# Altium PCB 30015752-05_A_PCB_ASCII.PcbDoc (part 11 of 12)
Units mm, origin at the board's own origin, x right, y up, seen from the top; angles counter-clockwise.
Board outline 100.05 x 72 mm, 10 copper layers (Top, GND_2, Signal_3, Signal_4, PWR_5, GND_6, Signal_7, Signal_8, GND_9, Bottom), stack 1.493 mm thick; 577 components, 546 nets, 2389 pads, 1412 vias.
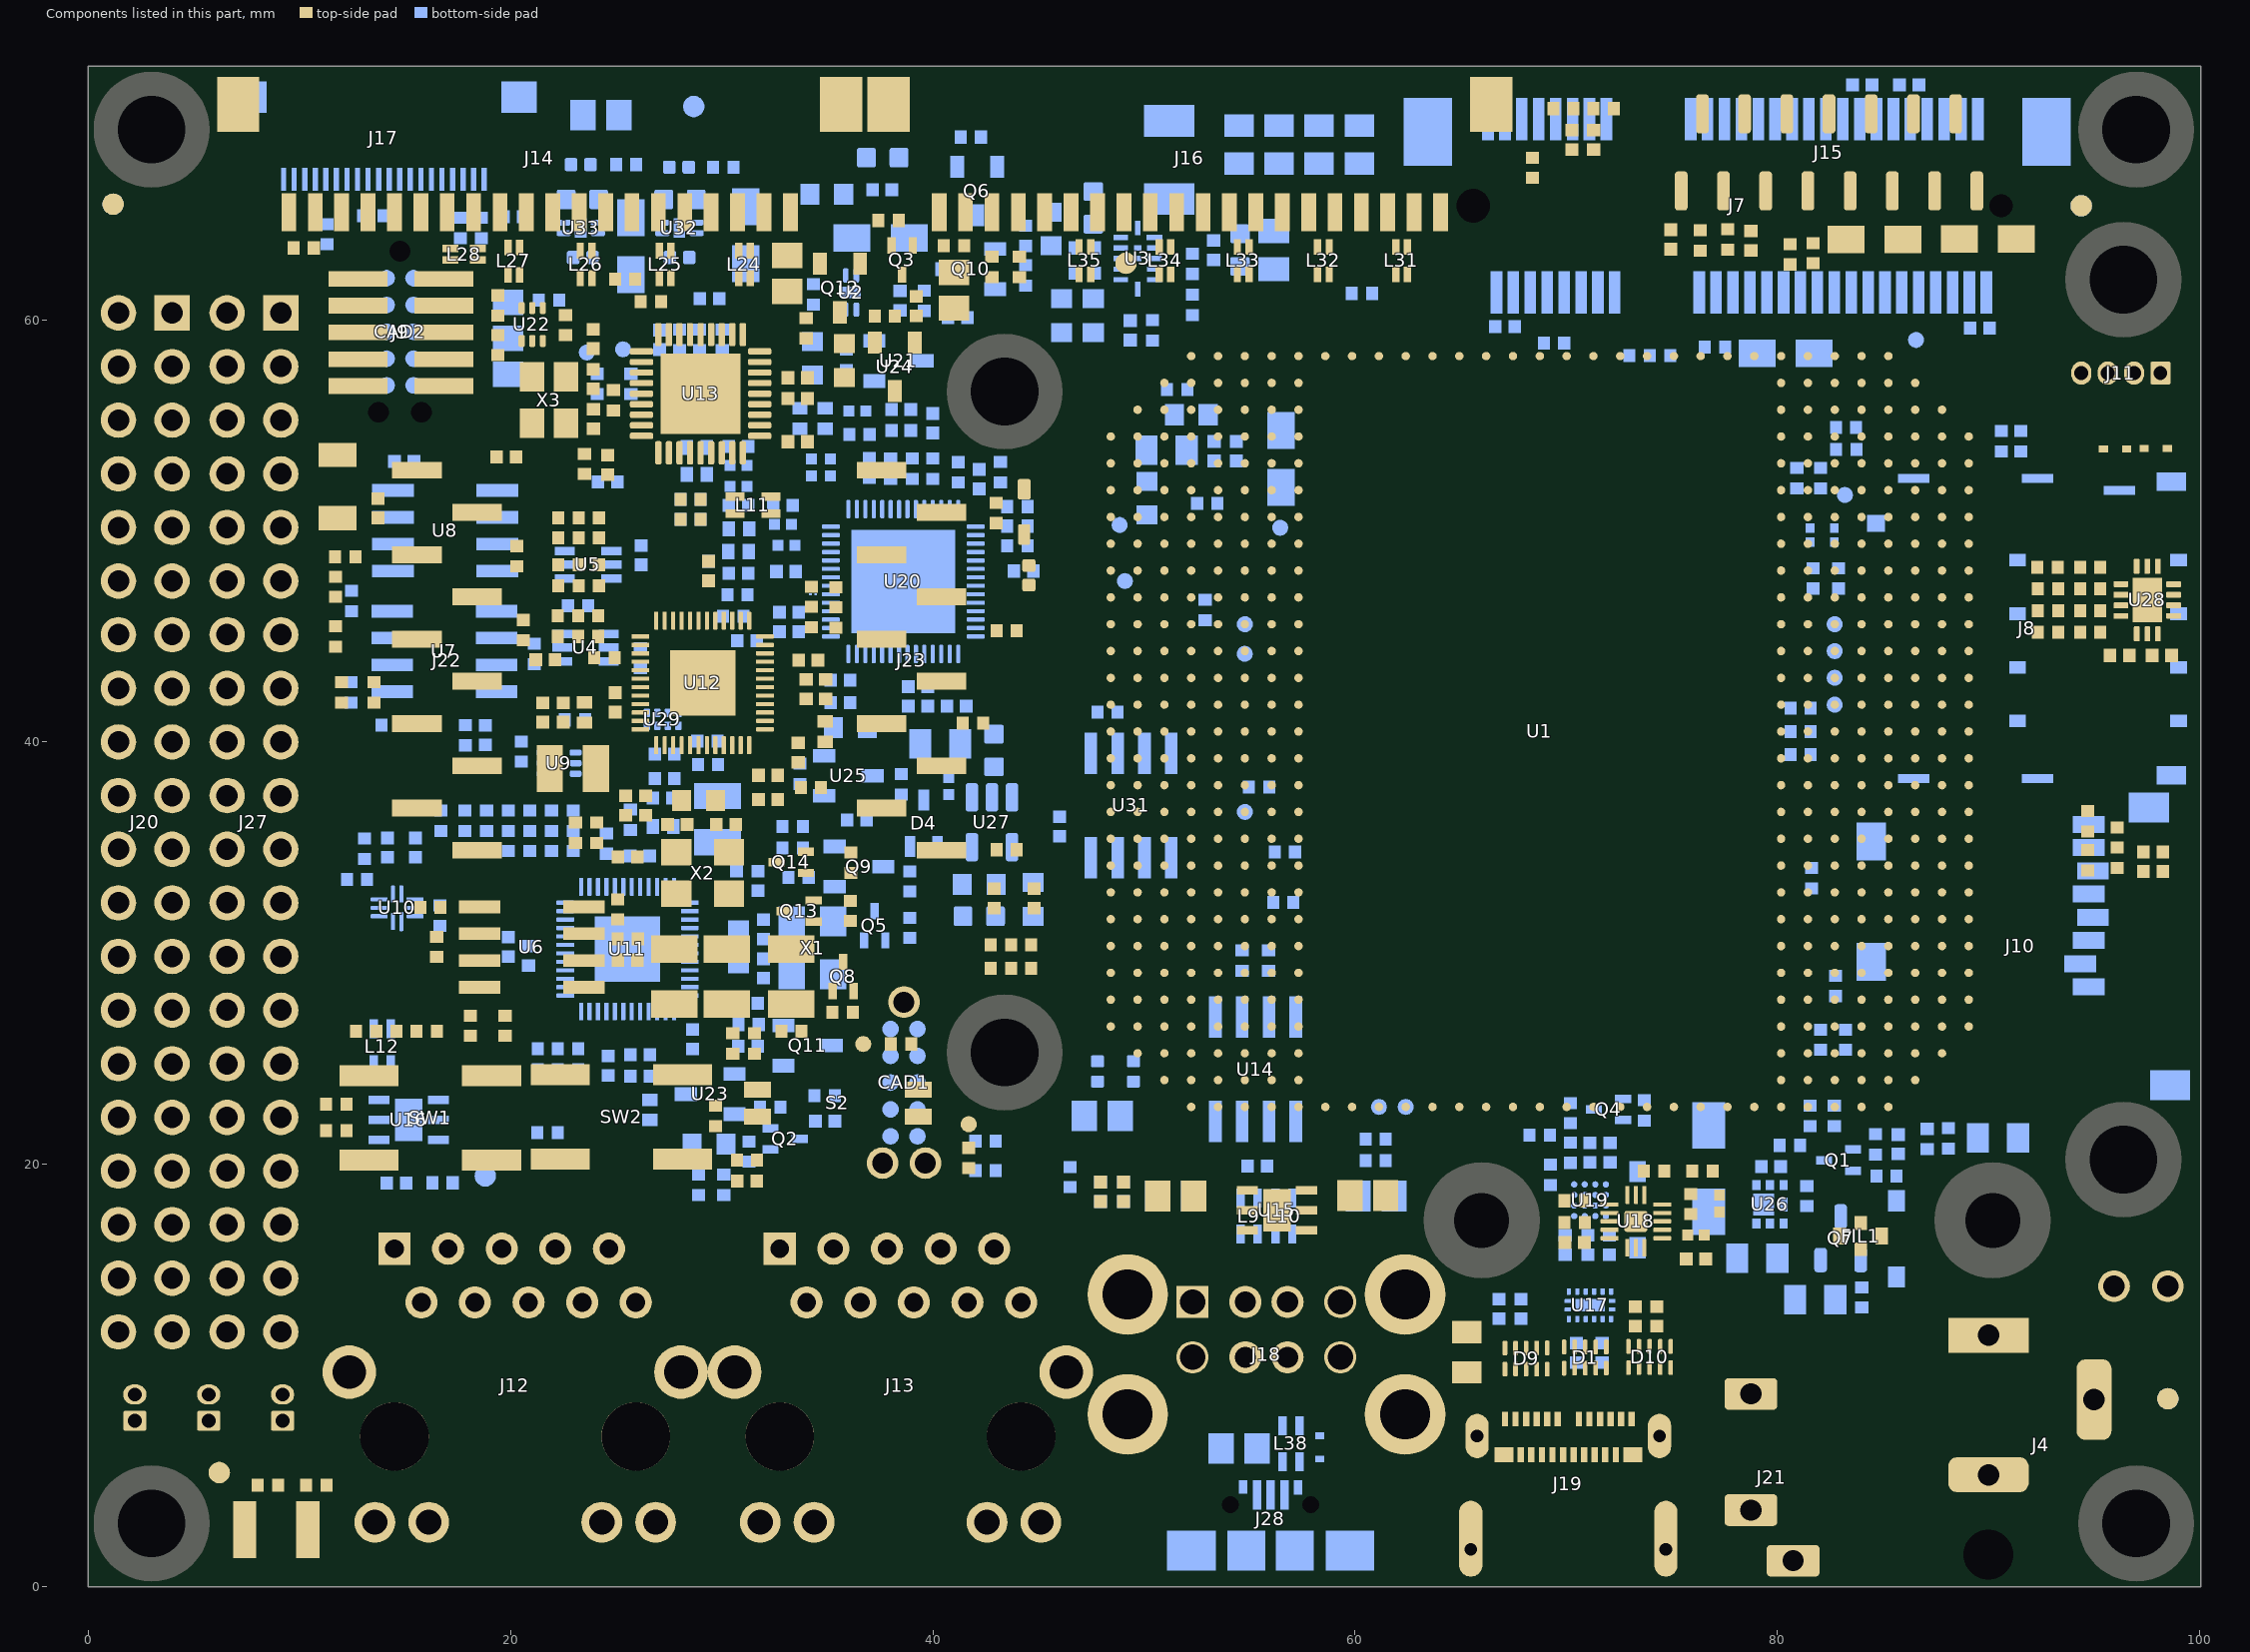
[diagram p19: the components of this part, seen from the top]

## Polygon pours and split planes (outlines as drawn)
PCIE_VCC on Bottom "Poly" (solid, remove dead copper, pour order 163): 61,68.6 53.85,68.6 53.45,68.2 49.65,68.2 49.45,68.4 49.45,70.575 49.65,70.775 60.475,70.775 61,70.25
GND on Bottom "Poly" (solid, remove dead copper, pour order 161): 52.85,64.55 52.85,66.5 52.95,66.6 60.8,66.6 60.8,65.35 60.5,65.05 55.25,65.05 55,64.8 53.65,64.8 53.4,64.55
NetC74_2 on Bottom "Poly" (solid, remove dead copper, pour order 160): 31.5,36.6 31.5,38.2 33.1,39.8 33.1,44.1 33.9,44.9 34.4,44.9 34.6,44.7 34.6,42.2 33.9,41.5 33.9,39.7 33.3,39.1 33.3,37 32.65,36.35 31.75,36.35
VIN_PROT on Bottom "Polysolid" (solid, remove dead copper, pour order 162): 79.75,18.55 78.65,18.55 78.55,18.65 78.55,19.45 78.75,19.65 79.5,19.65 79.5,20.15 75.55,20.15 75.3,19.9 75.3,15.35 75.525,15.125 78.425,15.125 78.425,17.475 78.65,17.7 79.75,17.7
TCGND on Signal_3 "Poly" (solid, remove dead copper, pour order 159): 64.7,9.2 64.7,1.9 65.2,1.4 74.9,1.4 75.4,1.9 75.4,8.715 74.658,9.457 64.957,9.457
GND on GND_2 (split plane): 99.648,0.402 0.402,0.402 0.402,64.782 0.509,64.675 0.667,64.569 0.843,64.496 1.03,64.459 1.275,64.459 1.471,64.498 1.656,64.575 1.823,64.686 1.964,64.827 2.075,64.994 2.152,65.179 2.191,65.375 2.191,65.475 2.191,65.575 2.152,65.771 2.075,65.956 1.964,66.123 1.823,66.264 1.656,66.375 1.471,66.452 1.275,66.491 1.075,66.491 0.879,66.452 0.694,66.375 0.527,66.264 0.402,66.139 0.402,71.598 99.648,71.598
VDDH1 on PWR_5 (split plane): 23.171,25.1 23.18,25.05 23.208,25.008 23.508,24.708 23.55,24.68 23.6,24.671 25.087,24.671 25.137,24.68 25.179,24.708 26.141,25.671 31.381,25.671 31.381,24.964 30.796,24.379 26.85,24.379 26.8,24.37 26.758,24.342 26.146,23.729 20.954,23.729 19.929,24.754 19.929,25.846 20.354,26.271 23.171,26.271
5V on PWR_5 (split plane): 21.271,70.6 21.28,70.55 21.308,70.508 22.008,69.808 22.05,69.78 22.1,69.771 49.246,69.771 51.308,67.708 51.35,67.68 51.4,67.671 67.046,67.671 68.308,66.408 68.35,66.38 68.4,66.371 73.479,66.371 73.479,64.762 72.946,64.229 62.354,64.229 61.392,65.192 61.35,65.22 61.3,65.229 36.529,65.229 34.367,67.392 34.325,67.42 34.275,67.429 20.579,67.429 19.817,68.192 19.775,68.22 19.725,68.229 8.7,68.229 8.65,68.22 8.608,68.192 3.908,63.492 3.88,63.45 3.871,63.4 3.871,17.14 3.88,17.09 3.908,17.048 4.973,15.983 5.015,15.955 5.065,15.946 9.871,15.946 10.496,15.321 10.496,10.75 10.496,7.254 9.946,6.704 5.179,6.704 4.479,7.404 4.479,10.075 4.47,10.125 4.442,10.167 3.742,10.867 3.7,10.895 3.65,10.904 0.402,10.904 0.402,71.598 21.271,71.598
VIN_PROT on PWR_5 (split plane): 33.971,64.246 33.971,63.2 33.98,63.15 34.008,63.108 35.258,61.858 35.3,61.83 35.35,61.821 42.925,61.821 42.975,61.83 43.017,61.858 43.629,62.471 56.146,62.471 56.871,61.746 56.871,61.059 56.871,60.654 56.008,59.792 55.98,59.75 55.971,59.7 55.971,37.6 55.971,32.6 55.98,32.55 56.008,32.508 56.908,31.608 56.95,31.58 57,31.571 57.918,31.571 57.918,24.22 57.918,24.121 57.925,24.051 57.926,24.042 57.949,23.967 58.025,23.783 58.062,23.713 58.081,23.69 58.112,23.653 58.253,23.512 58.283,23.487 58.313,23.462 58.383,23.425 58.567,23.349 58.625,23.331 58.642,23.326 58.721,23.318 78.779,23.318 78.858,23.326 78.875,23.331 78.933,23.349 79.117,23.425 79.171,23.453 79.171,16.526 78.774,16.129 72.8,16.129 72.75,16.12 72.708,16.092 71.196,14.579 70.329,14.579 70.329,18.6 70.32,18.65 70.292,18.692 69.692,19.292 69.65,19.32 69.6,19.329 52.354,19.329 50.479,21.204 50.479,35.025 50.47,35.075 50.442,35.117 49.667,35.892 49.625,35.92 49.575,35.929 45.954,35.929 45.629,36.254 45.629,37.596 46.029,37.996 53.025,37.996 53.075,38.005 53.117,38.033 53.341,38.258 53.369,38.3 53.379,38.349 53.379,55.051 53.379,59.251 53.369,59.3 53.341,59.342 52.392,60.292 52.35,60.32 52.3,60.329 39.8,60.329 39.75,60.32 39.708,60.292 38.721,59.304 37.754,59.304 36.742,60.317 36.7,60.345 36.65,60.354 33.929,60.354 32.829,61.454 32.829,63.7 32.82,63.75 32.792,63.792 32.392,64.192 32.35,64.22 32.3,64.229 29.625,64.229 29.575,64.22 29.533,64.192 21.008,55.667 20.98,55.625 20.971,55.575 20.971,47.154 20.746,46.929 19.629,46.929 19.629,56.146 25.342,61.858 28.654,65.171 33.046,65.171
3V3_EXT on PWR_5 (split plane): 329 vertices, not listed, extent 0.402,0.402 99.648,67.971
VDDIO2 on PWR_5 (split plane): 25.533,50.958 25.575,50.93 25.625,50.921 33.771,50.921 33.771,41.229 29.954,41.229 25.892,45.292 25.85,45.32 25.8,45.329 22.275,45.329 22.225,45.32 22.183,45.292 21.458,44.567 21.43,44.525 21.421,44.475 21.421,38.004 20.946,37.529 17.3,37.529 17.25,37.52 17.208,37.492 15.108,35.392 15.08,35.35 15.071,35.3 15.071,33.2 15.08,33.15 15.108,33.108 15.308,32.908 15.35,32.88 15.4,32.871 16.6,32.871 16.65,32.88 16.692,32.908 17.192,33.408 17.22,33.45 17.229,33.5 17.229,34.546 18.354,35.671 24.671,35.671 24.671,33.854 24.246,33.429 20,33.429 19.95,33.42 19.908,33.392 17.946,31.429 14.354,31.429 13.429,32.354 13.429,36.346 13.954,36.871 15.3,36.871 15.35,36.88 15.392,36.908 16.342,37.858 16.37,37.9 16.379,37.95 16.379,39.171 18.25,39.171 18.3,39.18 18.342,39.208 19.592,40.458 19.62,40.5 19.629,40.55 19.629,41.4 19.629,46.671 20.8,46.671 20.85,46.68 20.892,46.708 21.192,47.008 21.22,47.05 21.229,47.1 21.229,51.671 24.821,51.671
5V on PWR_5 (split plane): 19.923,62.397 19.923,61.8 19.923,61.303 17.71,59.09 17.682,59.049 17.673,59 17.673,55.15 17.673,53.075 17.682,53.026 17.71,52.985 18.66,52.035 18.701,52.007 18.75,51.998 19.371,51.998 19.371,46.8 19.371,41.4 19.371,40.604 18.196,39.429 16.377,39.429 16.377,40.372 16.528,40.523 18.1,40.523 18.149,40.532 18.19,40.56 18.64,41.01 18.668,41.051 18.677,41.1 18.677,49.35 18.668,49.399 18.64,49.44 16.577,51.503 16.577,53.047 17.09,53.56 17.118,53.601 17.127,53.65 17.127,61.45 17.127,62.047 17.678,62.598 19.722,62.598
1V8_EXT on PWR_5 (split plane): 29.808,41.008 29.85,40.98 29.9,40.971 33.771,40.971 33.771,35.8 33.771,33.754 33.746,33.729 33.059,33.729 32.429,34.359 32.429,36 32.42,36.05 32.392,36.092 24.592,43.892 24.55,43.92 24.5,43.929 23.7,43.929 23.65,43.92 23.608,43.892 23.408,43.692 23.38,43.65 23.371,43.6 23.371,43.417 23.371,41.9 23.371,41 23.371,35.929 18.3,35.929 18.25,35.92 18.208,35.892 17.008,34.692 16.98,34.65 16.971,34.6 16.971,33.554 16.546,33.129 15.454,33.129 15.329,33.254 15.329,35.246 17.354,37.271 21,37.271 21.05,37.28 21.092,37.308 21.642,37.858 21.67,37.9 21.679,37.95 21.679,44.421 22.329,45.071 25.746,45.071
NetC90_2 on PWR_5 (split plane): 32.571,63.646 32.571,61.4 32.58,61.35 32.608,61.308 33.771,60.146 33.771,57.2 33.771,51.179 25.679,51.179 24.967,51.892 24.925,51.92 24.875,51.929 21.229,51.929 21.229,55.521 29.679,63.971 32.246,63.971
NetC56_2 on PWR_5 (split plane): 31.381,32.436 31.381,25.929 26.087,25.929 26.038,25.92 25.996,25.892 25.033,24.929 23.654,24.929 23.429,25.154 23.429,27.446 26.392,30.408 26.42,30.45 26.429,30.5 26.429,34 26.42,34.05 26.392,34.092 26.092,34.392 26.05,34.42 26,34.429 24.929,34.429 24.929,35.671 28.146,35.671
3V3_ETH on PWR_5 (split plane): 32.171,35.946 32.171,34.306 32.18,34.256 32.208,34.214 32.914,33.508 32.956,33.48 33.006,33.471 33.8,33.471 33.85,33.48 33.892,33.508 33.992,33.608 34.02,33.65 34.029,33.7 34.029,35.8 34.029,40.971 36.271,40.971 36.271,39.254 35.708,38.692 35.68,38.65 35.671,38.6 35.671,36.2 35.671,23.354 35.346,23.029 29,23.029 28.95,23.02 28.908,22.992 28.208,22.292 28.18,22.25 28.171,22.2 28.171,20.729 26.679,20.729 26.329,21.079 26.329,23.546 26.904,24.121 30.85,24.121 30.9,24.13 30.942,24.158 31.602,24.819 31.63,24.861 31.64,24.911 31.64,32.489 31.63,32.539 31.602,32.581 28.292,35.892 28.25,35.92 28.2,35.929 23.629,35.929 23.629,41 23.629,43.417 23.629,43.546 23.754,43.671 24.446,43.671
USBC_VBUS on PWR_5 (split plane): 77.071,12.554 72.608,8.092 72.58,8.05 72.571,8 72.571,6.079 72.271,5.779 71.125,5.779 71.075,5.77 71.033,5.742 70.446,5.154 69.104,5.154 68.542,5.717 68.5,5.745 68.45,5.754 68.204,5.754 67.979,5.979 67.979,9.896 70.292,12.208 70.32,12.25 70.329,12.3 70.329,14.321 71.25,14.321 71.3,14.33 71.342,14.358 72.854,15.871 77.071,15.871
VCC_SCU_1V8 on PWR_5 (split plane): 43.071,35.837 43.071,29.054 40.808,26.792 40.78,26.75 40.771,26.7 40.771,24.2 40.78,24.15 40.808,24.108 44.221,20.696 44.221,19.854 42.996,18.629 36.854,18.629 34.792,20.692 34.75,20.72 34.7,20.729 28.429,20.729 28.429,22.146 29.054,22.771 35.4,22.771 35.45,22.78 35.492,22.808 35.892,23.208 35.92,23.25 35.929,23.3 35.929,28.871 39.7,28.871 39.75,28.88 39.792,28.908 41.192,30.308 41.22,30.35 41.229,30.4 41.229,35.796 41.454,36.021 42.887,36.021
3V3_CODEC on PWR_5 (split plane): 44.271,51.521 44.271,43.554 40.046,39.329 36.529,39.329 36.529,40.971 38.4,40.971 38.45,40.98 38.492,41.008 41.292,43.808 41.32,43.85 41.329,43.9 41.329,52.071 43.721,52.071
1V8_CODEC on PWR_5 (split plane): 41.071,57.271 41.071,43.954 38.346,41.229 34.029,41.229 34.029,57.071 37.8,57.071 37.85,57.08 37.892,57.108 38.504,57.721 40.621,57.721
NetR4_1 on PWR_5 (split plane): 65.071,60.158 65.08,60.108 65.108,60.066 65.673,59.501 65.715,59.473 65.765,59.464 68.193,59.464 68.243,59.473 68.285,59.501 68.954,60.171 75.046,60.171 76.008,59.208 76.05,59.18 76.1,59.171 78.871,59.171 79.283,58.758 79.325,58.73 79.375,58.721 80.671,58.721 80.671,38.054 80.546,37.929 79.582,37.929 79.582,56.78 79.582,56.879 79.574,56.958 79.569,56.975 79.551,57.033 79.475,57.217 79.438,57.287 79.413,57.317 79.388,57.347 79.247,57.488 79.21,57.519 79.187,57.538 79.117,57.575 78.933,57.651 78.858,57.674 78.849,57.675 78.779,57.682 58.721,57.682 58.651,57.675 58.642,57.674 58.567,57.651 58.383,57.575 58.313,57.538 58.29,57.519 58.253,57.488 58.112,57.347 58.081,57.31 58.062,57.287 58.025,57.217 57.949,57.033 57.926,56.958 57.925,56.949 57.918,56.879 57.918,56.78 57.918,31.829 57.054,31.829 56.229,32.654 56.229,37.6 56.229,59.646 57.092,60.508 57.12,60.55 57.129,60.6 57.129,61.059 57.129,61.671 65.071,61.671
PCIE_VCC on PWR_5 (split plane): 99.648,42.829 95.954,42.829 95.053,43.73 95.053,56.9 95.043,56.95 95.015,56.992 93.065,58.942 93.023,58.97 92.974,58.979 79.429,58.979 79.017,59.392 78.975,59.42 78.925,59.429 76.154,59.429 75.192,60.392 75.15,60.42 75.1,60.429 68.9,60.429 68.85,60.42 68.808,60.392 68.139,59.722 65.819,59.722 65.329,60.212 65.329,61.671 76.925,61.671 76.975,61.68 77.017,61.708 77.817,62.508 77.845,62.55 77.854,62.6 77.854,65.92 77.845,65.969 77.817,66.011 77.236,66.592 77.194,66.62 77.145,66.629 68.454,66.629 67.192,67.892 67.15,67.92 67.1,67.929 51.454,67.929 49.392,69.992 49.35,70.02 49.3,70.029 22.154,70.029 21.529,70.654 21.529,71.598 99.648,71.598
GND on GND_6 (split plane): 99.648,0.402 0.402,0.402 0.402,71.598 99.648,71.598
GND on GND_9 (split plane): 99.648,0.402 0.402,0.402 0.402,64.782 0.509,64.675 0.667,64.569 0.843,64.496 1.03,64.459 1.275,64.459 1.471,64.498 1.656,64.575 1.823,64.686 1.964,64.827 2.075,64.994 2.152,65.179 2.191,65.375 2.191,65.475 2.191,65.575 2.152,65.771 2.075,65.956 1.964,66.123 1.823,66.264 1.656,66.375 1.471,66.452 1.275,66.491 1.075,66.491 0.879,66.452 0.694,66.375 0.527,66.264 0.402,66.139 0.402,71.598 99.648,71.598

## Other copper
Top:
  rectangle net GND: 17.525,33.85 19.175,34.95
  rectangle net GND: 55.65,14.8 56.95,19.475
  rectangle net GND: 6.2,2.4 7.8,3.5
  region net SHLD: 11.8,3.7 10.2,3.7 10.2,2.6 11.8,2.6
  text "30015752-05_A_TOP" at 65.7,61.025 h0.86
  text ".Layer_Name" at 41.25,-18.875 h2.54
Signal_3:
  text ".Layer_Name" at 41.25,-18.875 h2.54
Signal_8:
  text ".Layer_Name" at 41.047,-19 h2.54
Signal_4:
  text ".Layer_Name" at 41.25,-18.875 h2.54
Signal_7:
  text ".Layer_Name" at 41.25,-18.875 h2.54
Bottom:
  rectangle net PCIE_VCC: 84.52,70.995 85.87,71.42
  text "30015752-05_A_BOT" at 46.5,69.925 h1
  text ".Layer_Name" at 37.526,-19 h2.54
GND_2 (plane layer: these items are gaps in the copper):
  lines w0.8: 0,0 0,72 100.05,72 100.05,0 0,0 ; 58.32,24.121 58.32,24.22 58.32,56.78 58.32,56.879 58.396,57.063 58.537,57.204 58.721,57.28 78.779,57.28 78.963,57.204 79.104,57.063 79.18,56.879 79.18,56.78 79.18,24.22 79.18,24.121 79.104,23.937 78.963,23.796 78.779,23.72 58.721,23.72 58.537,23.796 58.396,23.937 58.32,24.121
  text "NEGATIVE IMAGE" at 41,-15 h2.54
  text ".Layer_Name" at 41.25,-18.875 h2.54
PWR_5 (plane layer: these items are gaps in the copper):
  lines w0.25: 16.25,39.3 16.25,40.425 16.475,40.65 18.1,40.65 18.55,41.1 18.55,49.35 16.45,51.45 16.45,53.1 17,53.65 17,61.45 17,62.1 17.625,62.725 19.775,62.725 20.05,62.45 20.05,61.8 20.05,61.25 17.8,59 17.8,55.15 17.8,53.075 18.75,52.125 19.475,52.125 19.5,52.1
  lines w0.254: -0.125,13.425 -0.125,10.775 3.65,10.775 4.35,10.075 4.35,7.35 5.125,6.575 10,6.575 10.625,7.2 10.625,10.75 10.625,15.375 9.925,16.075 5.065,16.075 4,17.14 4,63.4 8.7,68.1 ; 8.1,67.5 8.7,68.1 ; 21.2,51.8 24.875,51.8 25.625,51.05 33.9,51.05 ; 21.4,72 21.4,70.6 22.1,69.9 49.3,69.9 51.4,67.8 67.1,67.8 68.4,66.5 77.145,66.5 77.725,65.92 77.725,62.6 76.925,61.8 65.2,61.8 ; 23.5,35.8 23.5,41 23.5,43.417 ; 23.5,41.9 23.5,43.6 23.7,43.8 24.5,43.8 32.3,36 32.3,34.306 33.006,33.6 33.8,33.6 33.9,33.7 33.9,35.8 33.9,57.2 ; 24.8,34.3 26,34.3 26.3,34 26.3,30.5 23.3,27.5 23.3,25.1 ; 24.8,35.8 24.8,33.8 24.3,33.3 20,33.3 18,31.3 14.3,31.3 13.3,32.3 13.3,36.4 13.9,37 15.3,37 16.25,37.95 16.25,39.3 17.4,39.3 18.25,39.3 19.5,40.55 19.5,41.4 19.5,46.8 ; 31.511,25.8 26.087,25.8 25.087,24.8 23.6,24.8 23.3,25.1 ; 33.9,60.2 33.9,57.2 ; 35.8,29 39.7,29 41.1,30.4 41.1,35.85 41.4,36.15 42.941,36.15 43.2,35.891 43.2,29 40.9,26.7 40.9,24.2 44.35,20.75 44.35,19.8 43.05,18.5 36.8,18.5 34.7,20.6 28.3,20.6 ; 36.4,41.1 36.4,39.2 ; 41.2,52.2 43.775,52.2 44.4,51.575 44.4,43.5 40.1,39.2 36.4,39.2 ; 58.3,31.7 57,31.7 56.1,32.6 56.1,37.6 56.1,59.7 57,60.6 57,61.059 57,61.8 ; 73.608,66.5 73.608,64.708 73,64.1 62.3,64.1 61.3,65.1 36.475,65.1 34.275,67.3 20.525,67.3 19.725,68.1 8.7,68.1 ; 77.2,16 77.2,12.5 72.7,8 72.7,6.025 72.325,5.65 71.125,5.65 70.5,5.025 69.05,5.025 68.45,5.625 68.15,5.625 67.849,5.926 67.849,9.949 70.2,12.3 70.2,14.45 ; 79.18,37.8 80.6,37.8 80.8,38 80.8,58.85 ; 79.3,23.72 79.3,16.472 78.828,16 76.3,16 72.8,16 71.25,14.45 70.2,14.45 ; 92.375,58.85 79.375,58.85 ; 100.05,42.7 95.9,42.7 94.924,43.677 94.924,56.9 92.974,58.85 79.375,58.85 ; 19.5,46.8 19.5,56.2 25.25,61.95 28.6,65.3 32,65.3 33.1,65.3 34.1,64.3 34.1,63.2 35.35,61.95 42.925,61.95 43.575,62.6 56.2,62.6 57,61.8 ; 19.5,46.8 20.8,46.8 21.1,47.1 21.1,55.575 29.625,64.1 30.8,64.1 32.3,64.1 32.7,63.7 32.7,61.4 33.875,60.225 36.65,60.225 37.7,59.175 38.775,59.175 39.8,60.2 52.3,60.2 53.249,59.251 53.249,55.051 53.249,38.349 53.025,38.125 45.975,38.125 45.5,37.65 45.5,36.2 45.9,35.8 49.575,35.8 50.35,35.025 50.35,21.15 52.3,19.2 63.2,19.2 69.6,19.2 70.2,18.6 70.2,14.45 ; 23.3,25.1 23.3,26.4 20.3,26.4 19.8,25.9 19.8,24.7 20.9,23.6 26.2,23.6 ; 26.2,23.6 26.85,24.25 30.85,24.25 31.511,24.911 31.511,32.489 28.2,35.8 18.3,35.8 17.1,34.6 17.1,33.5 16.6,33 15.4,33 15.2,33.2 15.2,35.3 17.3,37.4 21,37.4 21.55,37.95 21.55,44.475 22.275,45.2 25.8,45.2 29.9,41.1 33.9,41.1 38.4,41.1 41.2,43.9 41.2,57.325 40.675,57.85 38.45,57.85 37.8,57.2 33.9,57.2 ; 26.2,23.6 26.2,21.025 26.625,20.6 28.3,20.6 ; 28.3,20.6 28.3,22.2 29,22.9 35.4,22.9 35.8,23.3 35.8,36.2 35.8,38.6 36.4,39.2 ; 57,61.8 65.2,61.8 ; 65.2,61.8 65.2,60.158 65.765,59.593 68.193,59.593 68.9,60.3 75.1,60.3 76.1,59.3 78.925,59.3 79.375,58.85
  lines w0.8: 0,0 0,72 100.05,72 100.05,0 0,0 ; 58.32,24.121 58.32,24.22 58.32,56.78 58.32,56.879 58.396,57.063 58.537,57.204 58.721,57.28 78.779,57.28 78.963,57.204 79.104,57.063 79.18,56.879 79.18,56.78 79.18,24.22 79.18,24.121 79.104,23.937 78.963,23.796 78.779,23.72 58.721,23.72 58.537,23.796 58.396,23.937 58.32,24.121
  text "NEGATIVE IMAGE" at 41,-15 h2.54
  text ".Layer_Name" at 41.25,-18.875 h2.54
GND_6 (plane layer: these items are gaps in the copper):
  lines w0.8: 0,0 0,72 100.05,72 100.05,0 0,0 ; 58.32,24.121 58.32,24.22 58.32,56.78 58.32,56.879 58.396,57.063 58.537,57.204 58.721,57.28 78.779,57.28 78.963,57.204 79.104,57.063 79.18,56.879 79.18,56.78 79.18,24.22 79.18,24.121 79.104,23.937 78.963,23.796 78.779,23.72 58.721,23.72 58.537,23.796 58.396,23.937 58.32,24.121
  text "NEGATIVE IMAGE" at 41,-15 h2.54
  text ".Layer_Name" at 41.25,-18.875 h2.54
GND_9 (plane layer: these items are gaps in the copper):
  lines w0.8: 0,0 0,72 100.05,72 100.05,0 0,0 ; 58.32,24.121 58.32,24.22 58.32,56.78 58.32,56.879 58.396,57.063 58.537,57.204 58.721,57.28 78.779,57.28 78.963,57.204 79.104,57.063 79.18,56.879 79.18,56.78 79.18,24.22 79.18,24.121 79.104,23.937 78.963,23.796 78.779,23.72 58.721,23.72 58.537,23.796 58.396,23.937 58.32,24.121
  text "NEGATIVE IMAGE" at 41,-15 h2.54
  text ".Layer_Name" at 41.25,-18.875 h2.54

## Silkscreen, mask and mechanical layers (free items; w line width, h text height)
Top Overlay:
  circle w0.6: c85.25,19.025 r0.3
  circle w0.254: c24.875,28.35 r0.025
  circle w0.254: c26.925,38.85 r0.025
  circle w0.254: c26.1,53.05 r0.025
  circle w0.254: c20.1,60.975 r0.025
  circle w0.254: c39.55,21.3 r0.025
  circle w0.254: c54.375,19.275 r0.025
  circle w0.254: c75.25,16.55 r0.025
  circle w0.254: c69.4,11.55 r0.025
  circle w0.254: c70.125,9.55 r0.025
  circle w0.254: c73.225,9.65 r0.025
  circle w0.254: c99.575,45.95 r0.025
  circle w0.254: c67,8.7 r0.025
  lines w0.25: 10.075,49.075 11.075,49.075 ; 10.475,23.475 11.475,23.475 ; 10.575,36.05 11.575,36.05 ; 15.8,35.95 15.8,27.655 40.184,27.655 40.184,32 ; 15.8,37.95 15.8,39.7 ; 15.8,41.95 15.8,43.7 ; 15.8,45.95 15.8,47.7 ; 15.8,49.95 15.8,51.7 ; 16.365,54.696 21.008,58.675 23.45,58.675 ; 32.583,58.675 35.025,58.675 ; 38.656,55.851 40.184,54.068 40.184,51.7 ; 40.184,35.95 40.184,37.7 ; 40.184,39.95 40.184,41.7 ; 40.184,43.95 40.184,45.7 ; 40.184,47.95 40.184,49.7
  lines w0.254: 0.5,63.275 4.75,63.275 ; 5.6,63.275 9.2,63.275 ; 83.175,19.025 84.675,19.025 ; 83.175,19.825 83.975,19.825 ; 83.575,19.425 83.575,20.225 ; 85.224,20.025 cw(c85.25,19.025) 85.275,18.025 ; 86.25,19.025 87.75,19.025 ; 86.975,19.625 87.775,19.625
  text "MIPI CAMERA" at 73.075,70.725 h1.5
  text "J20" at 1.85,63.5 h1.5
  text "J27" at 5.925,63.5 h1.5
  text "DSI1" at 44.5,62.825 h1.5
  text "DSI0" at 20.925,62.6 h1.5
  text "A" at 0.975,62.025 h1.5
  text "B" at 3.55,62.025 h1.5
  text "C" at 6.15,62.025 h1.5
  text "D" at 8.7,62.025 h1.5
  text "ConnectCore® 8X SBC PRO" at 81.825,60.075 h1.5
  text "SWD" at 13.55,53.925 h1.5
  text "CONS." at 94.075,53.025 h1.5
  text "6" at 10.675,47.125 h1.5
  text "10" at 10.65,36.925 h1.5
  text "XBEE" at 20.45,33.1 h1.8
  text "LED1" at 29.075,31.075 h1.5
  text "LED0" at 25.775,31.025 h1.5
  text "PWR" at 36.875,29.625 h1.5
  text "LED" at 36.875,28.525 h1.5
  text "15" at 10.6,24.225 h1.5
  text "BOOT" at 33.675,19.425 h1.5
  text "RESET" at 22.9,18.05 h1.5
  text "ETH2" at 39.25,18.025 h1.5
  text "ON/OFF" at 14.075,17.975 h1.5
  text "ETH1" at 10.7,17.9 h1.5
  text "USB 2.0" at 48.75,16.375 h1.5
  text "PWR" at 88.225,13.075 h1.5
  text "5VDC" at 94.2,12.725 h1.5 r90
  text "20" at 10.65,11.625 h1.5
  text "C" at 6.3,9.725 h1.5
  text "D" at 8.85,9.7 h1.5
  text "A" at 1.125,9.675 h1.5
  text "B" at 3.7,9.675 h1.5
  text "3V3" at 0.925,5.675 h1
  text "5V" at 4.025,5.625 h1
  text "LICELL" at 7.725,5.525 h1
  text "USB 3.0" at 64.6,1.3 h1.5 r90
  text "AUDIO" at 76.55,1.125 h1.5 r90
  text ".Layer_Name" at 41.5,-18.75 h2.54
Bottom Overlay:
  circle w0.254: c42.9,50.2 r0.025
  circle w0.254: c19.85,52.475 r0.025
  circle w0.254: c19.775,46.775 r0.025
  circle w0.254: c22.525,47.275 r0.025
  circle w0.254: c21.8,43.425 r0.025
  circle w0.254: c23.5,39.775 r0.025
  circle w0.254: c12.2,20.65 r0.025
  circle w0.254: c52.675,27.75 r0.025
  circle w0.254: c46.9,40.45 r0.025
  circle w0.254: c51.075,64.25 r0.025
  circle w0.254: c72.05,19.575 r0.025
  circle w0.254: c72.65,12.3 r0.025
  lines w0.25: 10.475,23.475 11.475,23.475 ; 10.5,49.075 11.5,49.075 ; 10.575,36.05 11.575,36.05
  lines w0.254: 1.725,8.475 2.675,8.475 ; 5.225,8.475 6.175,8.475 ; 8.725,8.475 9.675,8.475 ; 46.7,8.525 48.263,10.088 ; 51.325,12.825 51.325,14.175 ; 55.8,10.2 55.8,11.55 ; 55.8,12.825 55.8,14.175 ; 60.25,12.825 60.25,14.2 ; 63.075,16.075 64.638,14.512 ; 95.025,56.975 95.025,57.925 ; 96.275,56.975 96.275,57.925 ; 97.525,56.975 97.525,57.925
  text "CSI" at 6.075,63.35 h2
  text "1" at 11.6,59.975 h1.5
  text "PCI EXPRESS / MINI CARD" at 65.625,57.925 h2
  text "SWD" at 17.275,57 h2 r270
  text "MICRO SIM" at 98.7,53.2 h1.4
  text "5" at 11.325,49.9 h1.5
  text "10" at 11.65,37.05 h1.5
  text "MICRO SD" at 79.45,29.55 h1.8 r270
  text "15" at 11.625,24.3 h1.5
  text "JTAG" at 40.425,17.698 h2
  text "20" at 11.775,11.625 h1.5
  text "C" at 6.95,9.725 h1.5
  text "D" at 9.5,9.7 h1.5
  text "A" at 1.9,9.675 h1.5
  text "B" at 4.325,9.675 h1.5
  text "USB OTG" at 59.025,8.475 h2
  text ".Layer_Name" at 69.25,-19.25 h2.54
Top Paste:
  text ".Layer_Name" at 39.548,-18.889 h2.54
Bottom Paste:
  text ".Layer_Name" at 37.409,-19.018 h2.54
Top Solder:
  text ".Layer_Name" at 38.026,-18.881 h2.54
Bottom Solder:
  text ".Layer_Name" at 37.014,-19.018 h2.54
Board Outline:
  the board outline again, w0.25
Top Assembly:
  lines w0.067: 151.171,-42.46 151.171,-42.386 151.523,-42.386 151.523,-42.46 151.387,-42.46 151.387,-42.807 151.306,-42.807 151.306,-42.46 151.171,-42.46 ; 151.588,-42.807 151.588,-42.386 151.689,-42.386 151.752,-42.538 151.788,-42.645 151.794,-42.645 151.83,-42.538 151.891,-42.386 151.992,-42.386 151.992,-42.807 151.914,-42.807 151.914,-42.621 151.923,-42.479 151.917,-42.479 151.821,-42.742 151.76,-42.742 151.662,-42.479 151.657,-42.479 151.666,-42.621 151.666,-42.807 151.588,-42.807
  lines w0.381: 68.834,-69.85 227.584,-69.85 ; 68.834,-65.024 119.634,-65.024 ; 68.834,-55.372 119.634,-55.372 ; 119.634,-76.2 119.634,-31.75 ; 119.634,-60.198 68.834,-60.198 227.584,-60.198 ; 119.634,-44.45 227.584,-44.45 ; 129.286,-69.85 129.286,-60.198 ; 145.034,-76.2 145.034,-69.85 ; 157.734,-69.85 157.734,-60.198 ; 183.134,-76.2 183.134,-69.85 ; 217.932,-69.85 217.932,-60.198 ; 68.834,-76.2 68.834,-31.75 227.584,-31.75 227.584,-76.2 68.834,-76.2
  lines w0.762: -30.988,22.098 -20.32,22.098 ; 103.632,-81.28 103.632,-76.2 ; 227.584,22.098 238.252,22.098 ; -20.32,-76.2 -20.32,120.396 227.584,120.396 227.584,-76.2 -20.32,-76.2
  text "2" at 27.432,122.428 h4.57
  text "1" at 179.832,122.428 h4.57
  text "B" at -25.908,75.438 h7.11
  text "B" at 230.632,75.438 h7.11
  text "1. Assemble in accordance with IPC-A-610, class 2." at 110,68 h5
  text ".Layer_Name" at 37.75,-19 h2.54
  text "CAD GENERATED:" at 169.164,-30.48 h1.27
  text ".pcb_File_Name_No_Path" at 184.658,-30.48 h2.17
  text "A" at -25.908,-31.242 h7.11
  text "A" at 230.632,-31.242 h7.11
  text "EXCEPT AS MAY BE OTHERWISE PROVIDED BY" at 70.104,-34.544 h2.17
  text "WIRELESS DESIGN SERVICES" at 164.084,-36.068 h2.54
  text "CONTRACT, THIS DOCUMENT IS THE PROPERTY" at 70.104,-36.576 h2.17
  text "OF DIGI INTERNATIONAL.  IF RELEASED TO OTHER" at 70.104,-38.608 h2.17
  text "11001 Bren Road East" at 164.084,-39.624 h2.54
  text "SOURCES, IT SHALL BE RECEIVED BY SUCH" at 70.104,-40.64 h2.17
  text "SOURCES IN TOTAL CONFIDENCE AND SHALL NOT" at 70.104,-42.672 h2.17
  text "Minnetonka, MN 55343" at 164.592,-43.18 h2.54
  text "BE RELEASED TO ANY THIRD PARTY OR PARTIES," at 70.104,-44.704 h2.17
  text "NOR USED FOR MANUFACTURE OR SALE OF THE" at 70.104,-46.736 h2.17
  text "ARTICLES WITHOUT PRIOR WRITTEN" at 70.104,-48.768 h2.17
  text "DIGI INTERNATIONAL" at 160.02,-49.276 h2.54
  text "AUTHORIZATION." at 70.104,-50.8 h2.17
  text "ConnectCore for i.MX8x" at 155.448,-53.34 h2.54
  text "ENGINEER" at 69.596,-57.404 h1.27
  text "SINGLE BOARD COMPUTER PRO (SBC)" at 147.32,-57.404 h2.54
  text "Sebastien Meyer" at 86.36,-58.42 h1.27
  text "PCB DESIGNER" at 69.596,-62.484 h1.27
  text "SIZE" at 122.936,-62.484 h1.27
  text "CAGE NO." at 131.064,-62.484 h1.27
  text "ASSM NO." at 159.004,-62.484 h1.27
  text "REV." at 220.98,-62.484 h1.27
  text "Josh Flagstad" at 86.36,-63.5 h1.27
  text ".VariantName" at 180.34,-66.294 h2.54
  text "DATE" at 69.596,-67.056 h1.27
  text "A" at 123.444,-67.056 h2.54
  text "'.VariantRevision'" at 220.98,-67.056 h2.54
  text ".Print_Date" at 86.36,-68.072 h1.27
  text "JIRA EPIC:" at 69.596,-72.136 h1.27
  text "CC6UL-244" at 86.36,-73.66 h1.27
  text ".Print_Scale" at 120.904,-73.66 h1.27
  text "SVN HEAD REV:" at 146.304,-73.66 h1.27
  text ".VersionControl_RevNumber" at 162.052,-73.66 h1.27
  text "SHEET:" at 184.404,-73.66 h1.27
  text "1 OF 1" at 202.946,-73.66 h1.27
  text "2" at 27.432,-80.772 h4.57
  text "1" at 179.832,-80.772 h4.57
Bottom Assembly:
  lines w0.05: 90.25,12.25 95.5,12.25 95.5,19
  lines w0.067: 55.272,-42.807 55.35,-42.807 55.35,-42.621 55.341,-42.479 55.347,-42.479 55.443,-42.742 55.504,-42.742 55.602,-42.479 55.607,-42.479 55.598,-42.621 55.598,-42.807 55.676,-42.807 55.676,-42.386 55.575,-42.386 55.512,-42.538 55.476,-42.645 55.47,-42.645 55.434,-42.538 55.373,-42.386 55.272,-42.386 55.272,-42.807 ; 55.741,-42.46 55.877,-42.46 55.877,-42.807 55.958,-42.807 55.958,-42.46 56.093,-42.46 56.093,-42.386 55.741,-42.386 55.741,-42.46
  lines w0.381: -20.32,-69.85 138.43,-69.85 ; -20.32,-60.198 138.43,-60.198 87.63,-60.198 ; -20.32,-44.45 87.63,-44.45 ; -10.668,-69.85 -10.668,-60.198 ; 24.13,-76.2 24.13,-69.85 ; 49.53,-69.85 49.53,-60.198 ; 62.23,-76.2 62.23,-69.85 ; 77.978,-69.85 77.978,-60.198 ; 87.63,-76.2 87.63,-31.75 ; 87.63,-65.024 138.43,-65.024 ; 87.63,-55.372 138.43,-55.372 ; -20.32,-76.2 -20.32,-31.75 138.43,-31.75 138.43,-76.2 -20.32,-76.2
  lines w0.762: -30.988,22.098 -20.32,22.098 ; 103.632,-81.28 103.632,-76.2 ; 227.584,22.098 238.252,22.098 ; -20.32,-76.2 -20.32,120.396 227.584,120.396 227.584,-76.2 -20.32,-76.2
  text "1" at 27.432,122.428 h4.57
  text "2" at 179.832,122.428 h4.57
  text "B" at -23.368,75.438 h7.11
  text "B" at 233.172,75.438 h7.11
  text "1. Assemble in accordance with IPC-A-610, class 2." at 212,68 h5
  text ".Layer_Name" at 70.324,-19.016 h2.54
  text ".pcb_File_Name_No_Path" at 22.606,-30.48 h2.17
  text "CAD GENERATED:" at 38.1,-30.48 h1.27
  text "A" at -23.368,-31.242 h7.11
  text "A" at 233.172,-31.242 h7.11
  text "EXCEPT AS MAY BE OTHERWISE PROVIDED BY" at 137.16,-34.544 h2.17
  text "WIRELESS DESIGN SERVICES" at 43.18,-36.068 h2.54
  text "CONTRACT, THIS DOCUMENT IS THE PROPERTY" at 137.16,-36.576 h2.17
  text "OF DIGI INTERNATIONAL.  IF RELEASED TO OTHER" at 137.16,-38.608 h2.17
  text "11001 Bren Road East" at 43.18,-39.624 h2.54
  text "SOURCES, IT SHALL BE RECEIVED BY SUCH" at 137.16,-40.64 h2.17
  text "SOURCES IN TOTAL CONFIDENCE AND SHALL NOT" at 137.16,-42.672 h2.17
  text "Minnetonka, MN 55343" at 42.672,-43.18 h2.54
  text "BE RELEASED TO ANY THIRD PARTY OR PARTIES," at 137.16,-44.704 h2.17
  text "NOR USED FOR MANUFACTURE OR SALE OF THE" at 137.16,-46.736 h2.17
  text "ARTICLES WITHOUT PRIOR WRITTEN" at 137.16,-48.768 h2.17
  text "DIGI INTERNATIONAL" at 47.244,-49.276 h2.54
  text "AUTHORIZATION." at 137.16,-50.8 h2.17
  text "ConnectCore for i.MX8x" at 51.816,-53.34 h2.54
  text "SINGLE BOARD COMPUTER PRO (SBC)" at 59.944,-57.404 h2.54
  text "ENGINEER" at 137.668,-57.404 h1.27
  text "Sebastien Meyer" at 120.904,-58.42 h1.27
  text "REV." at -13.716,-62.484 h1.27
  text "ASSM NO." at 48.26,-62.484 h1.27
  text "CAGE NO." at 76.2,-62.484 h1.27
  text "SIZE" at 84.328,-62.484 h1.27
  text "PCB DESIGNER" at 137.668,-62.484 h1.27
  text "Josh Flagstad" at 120.904,-63.5 h1.27
  text ".VariantName" at 26.924,-66.294 h2.54
  text "'.VariantRevision'" at -13.716,-67.056 h2.54
  text "A" at 83.82,-67.056 h2.54
  text "DATE" at 137.668,-67.056 h1.27
  text ".Print_Date" at 120.904,-68.072 h1.27
  text "JIRA EPIC:" at 137.668,-72.136 h1.27
  text "1 OF 1" at 4.318,-73.66 h1.27
  text "SHEET:" at 22.86,-73.66 h1.27
  text ".VersionControl_RevNumber" at 45.212,-73.66 h1.27
  text "SVN HEAD REV:" at 60.96,-73.66 h1.27
  text ".Print_Scale" at 86.36,-73.66 h1.27
  text "CC6UL-244" at 120.904,-73.66 h1.27
  text "1" at 27.432,-80.772 h4.57
  text "2" at 179.832,-80.772 h4.57
Cavity Solder Mask:
  lines w0.25: 0,0 0,72 100,72 100,0 0,0
Panel:
  lines w0.1: 58.32,24.243 58.32,56.71 cw(c58.9,56.71) 58.9,57.29 ; 58.327,24.243 ccw(c58.85,24.243) 58.85,23.72 78.682,23.72 ; 58.871,57.29 78.618,57.29 ; 78.618,57.287 cw(c78.618,56.725) 79.18,56.725 79.18,24.225 cw(c78.682,24.225) 78.682,23.727 ; 160.97,24.243 160.97,56.71 cw(c161.55,56.71) 161.55,57.29 ; 160.977,24.243 ccw(c161.5,24.243) 161.5,23.72 181.332,23.72 ; 161.521,57.29 181.268,57.29 ; 181.268,57.287 cw(c181.268,56.725) 181.83,56.725 181.83,24.225 cw(c181.332,24.225) 181.332,23.727 ; 263.37,24.243 263.37,56.71 cw(c263.95,56.71) 263.95,57.29 ; 263.377,24.243 ccw(c263.9,24.243) 263.9,23.72 283.732,23.72 ; 263.921,57.29 283.668,57.29 ; 283.668,57.287 cw(c283.668,56.725) 284.23,56.725 284.23,24.225 cw(c283.732,24.225) 283.732,23.727
  lines w0.25: -2.5,0 ccw(c-1.25,0) 0,0 ; 6.25,-4 cw(c6.25,-2.75) 5,-2.75 5,-1.25 ; 108.75,-4 cw(c108.75,-2.75) 107.5,-2.75 107.5,-1.25 ; 211.25,-4 cw(c211.25,-2.75) 210,-2.75 210,-1.25 ; 272.55,-4 306.25,-4 ccw(c306.25,-2.75) 307.5,-2.75 307.5,10 ccw(c306.25,10) 305,10 305,0 ; 272.55,0 305,0 ; 298,-4 272.475,-4 198.75,-4 ; 301.25,-4 ccw(c301.25,-2.75) 302.5,-2.75 302.5,-1.25 ; 307.5,0 cw(c306.25,0) 305,0 ; 0,0 0,10 ccw(c-1.25,10) -2.5,10 -2.5,-2.75 ccw(c-1.25,-2.75) -1.25,-4 67.475,-4 96.25,-4 ; 0,0 67.475,0 100,0 ; 5,-1.25 cw(c6.25,-1.25) 6.25,0 ccw(c6.25,-1.25) 5,-1.25 ; 96.25,-4 ccw(c96.25,-2.75) 97.5,-2.75 97.5,-1.25 ; 96.25,-4 169.975,-4 198.75,-4 ; 97.5,-1.25 ccw(c96.25,-1.25) 96.25,0 cw(c96.25,-1.25) 97.5,-1.25 ; 100,0 ccw(c101.25,0) 102.5,0 ; 100,0 100,10 ; 100,0 100,10 ; 100,10 cw(c101.25,10) 102.5,10 102.5,0 ; 102.5,0 169.975,0 202.5,0 ; 107.5,-1.25 cw(c108.75,-1.25) 108.75,0 ccw(c108.75,-1.25) 107.5,-1.25 ; 198.75,-4 ccw(c198.75,-2.75) 200,-2.75 200,-1.25 ; 200,-1.25 ccw(c198.75,-1.25) 198.75,0 cw(c198.75,-1.25) 200,-1.25 ; 202.5,0 ccw(c203.75,0) 205,0 ; 202.5,0 202.5,10 cw(c203.75,10) 205,10 205,0 ; 205,0 272.475,0 305,0 ; 210,-1.25 cw(c211.25,-1.25) 211.25,0 ccw(c211.25,-1.25) 210,-1.25 ; 302.5,-1.25 ccw(c301.25,-1.25) 301.25,0 cw(c301.25,-1.25) 302.5,-1.25 ; -15,-11.5 320,-11.5 320,79.5 -15,79.5 -15,-11.5 ; -2.5,17.5 ccw(c-1.25,17.5) 0,17.5 0,54.5 ccw(c-1.25,54.5) -2.5,54.5 -2.5,17.5 ; -2.5,62 ccw(c-1.25,62) 0,62 0,72 10,72 ccw(c10,73.25) 10,74.5 0,74.5 ccw(c0,72) -2.5,72 -2.5,62 ; 17.5,72 cw(c17.5,73.25) 17.5,74.5 67.5,74.5 cw(c67.5,73.25) 67.5,72 17.5,72 ; 75,72 cw(c75,73.25) 75,74.5 112.54,74.5 cw(c112.54,73.25) 112.54,72 102.5,72 102.5,62 cw(c101.25,62) 100,62 100,72 75,72 ; 100,16.25 ccw(c101.25,16.25) 102.5,16.25 102.5,54.5 ccw(c101.25,54.5) 100,54.5 100,16.25 ; 120,72 cw(c120,73.25) 120,74.5 170,74.5 cw(c170,73.25) 170,72 120,72 ; 177.54,72 cw(c177.54,73.25) 177.54,74.5 215,74.5 cw(c215,73.25) 215,72 205,72 205,62 cw(c203.75,62) 202.5,62 202.5,72 177.54,72 ; 202.5,16.25 ccw(c203.75,16.25) 205,16.25 205,54.5 ccw(c203.75,54.5) 202.5,54.5 202.5,16.25 ; 222.5,72 cw(c222.5,73.25) 222.5,74.5 272.58,74.5 cw(c272.58,73.25) 272.58,72 222.5,72 ; 280.08,72 cw(c280.08,73.25) 280.08,74.5 305,74.5 cw(c305,72) 307.5,72 307.5,62 cw(c306.25,62) 305,62 305,72 280.08,72 ; 305,16.25 ccw(c306.25,16.25) 307.5,16.25 307.5,54.5 ccw(c306.25,54.5) 305,54.5 305,16.25
  text ".Layer_Name" at 41.25,-18.875 h2.54
PCB Name:
  text "CC8X SBC PRO Rev A" at 36.25,-24.125 h2.54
